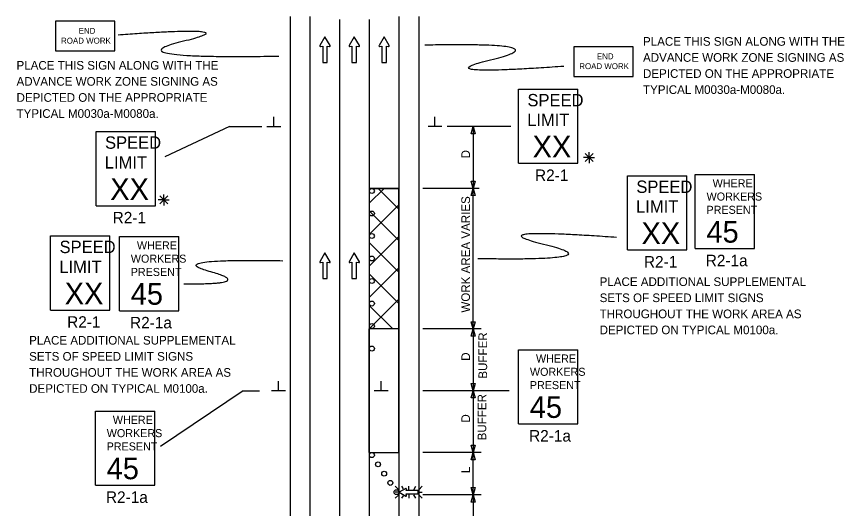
# Model space of a CAD drawing. Extents: x 16730 to 18475, y 5690 to 6927.
# Drawn here: x 16730 to 17399, y 6529 to 6927 of the extents above; entities that cross this region are included whole.
import ezdxf

# ---------------------------------------------------------------- set-up
doc = ezdxf.new("R2010")
doc.units = 0
for name, color, linetype in [('ALI_LEGAL_EX', 7, 'Continuous'), ('MT_SCRATCH_LEVEL_E', 7, 'Continuous'), ('PAVT_EDGE_EX', 7, 'Continuous'), ('TRAFFIC_SIGNS_PR', 7, 'Continuous'), ('TYPICAL_TEXT_DIMEN_PR', 7, 'Continuous')]:
    doc.layers.add(name, color=color, linetype=linetype)

msp = doc.modelspace()

# ---------------------------------------------------------------- linework, layer by layer
at = {"layer": 'ALI_LEGAL_EX'}
for p, q in [((16991.15, 6924.81), (16991.15, 6107.83)), ((17015.15, 6924.81), (17015.15, 6107.83))]:
    msp.add_line(p, q, dxfattribs=at)
for points in [[(16991.15, 6924.81), (16991.15, 6899.81)], [(17015.15, 6924.81), (17015.15, 6899.81)], [(16991.15, 6824.81), (16991.15, 6799.81)], [(17015.15, 6824.81), (17015.15, 6799.81)], [(16991.15, 6724.81), (16991.15, 6699.81)], [(17015.15, 6724.81), (17015.15, 6699.81)], [(16991.15, 6624.81), (16991.15, 6599.81)]]:
    msp.add_lwpolyline(points, dxfattribs=at)
at = {"layer": 'MT_SCRATCH_LEVEL_E'}
for p, q in [((16979.3, 6910.86), (16975.19, 6903.61)), ((16983.44, 6903.61), (16979.3, 6910.86)), ((17003, 6910.86), (16998.89, 6903.61)), ((17007.15, 6903.61), (17003, 6910.86)), ((17027.11, 6910.86), (17023, 6903.61)), ((17031.26, 6903.61), (17027.11, 6910.86)), ((16975.67, 6902.93), (16977.45, 6903.25)), ((16977.45, 6903.25), (16977.45, 6889.99)), ((16981.19, 6889.99), (16981.19, 6903.25)), ((16981.19, 6903.25), (16982.97, 6902.93)), ((16999.37, 6902.93), (17001.15, 6903.25)), ((17001.15, 6903.25), (17001.15, 6889.99)), ((17004.89, 6889.99), (17004.89, 6903.25)), ((17004.89, 6903.25), (17006.67, 6902.93)), ((17023.48, 6902.93), (17025.26, 6903.25)), ((17025.26, 6903.25), (17025.26, 6889.99)), ((17029, 6889.99), (17029, 6903.25)), ((17029, 6903.25), (17030.78, 6902.93)), ((16977.45, 6889.99), (16981.19, 6889.99)), ((17001.15, 6889.99), (17004.89, 6889.99)), ((17025.26, 6889.99), (17029, 6889.99)), ((16979.3, 6736.02), (16975.19, 6728.78)), ((16983.44, 6728.78), (16979.3, 6736.02)), ((17003, 6736.02), (16998.89, 6728.78)), ((17007.15, 6728.78), (17003, 6736.02)), ((16975.67, 6728.09), (16977.45, 6728.41)), ((16977.45, 6728.41), (16977.45, 6715.15)), ((16981.19, 6715.15), (16981.19, 6728.41)), ((16981.19, 6728.41), (16982.97, 6728.09)), ((16999.37, 6728.09), (17001.15, 6728.41)), ((17001.15, 6728.41), (17001.15, 6715.15)), ((17004.89, 6715.15), (17004.89, 6728.41)), ((17004.89, 6728.41), (17006.67, 6728.09)), ((16977.45, 6715.15), (16981.19, 6715.15)), ((17001.15, 6715.15), (17004.89, 6715.15))]:
    msp.add_line(p, q, dxfattribs=at)
for centre, start, end in [((16975.59, 6903.39), 150.42484, 279.96381), ((16983.04, 6903.39), 260.03619, 29.77312), ((16999.3, 6903.39), 150.42484, 279.96381), ((17006.74, 6903.39), 260.03619, 29.77312), ((17023.41, 6903.39), 150.42484, 279.96381), ((17030.85, 6903.39), 260.03619, 29.77312), ((16975.59, 6728.55), 150.42484, 279.96381), ((16983.04, 6728.55), 260.03619, 29.77312), ((16999.3, 6728.55), 150.42484, 279.96381), ((17006.74, 6728.55), 260.03619, 29.77312)]:
    msp.add_arc(centre, 0.463, start, end, dxfattribs=at)
at = {"layer": 'PAVT_EDGE_EX'}
for p, q in [((16951.15, 6927.15), (16951.15, 6107.83)), ((16967.15, 6927.15), (16967.15, 6107.83)), ((17039.15, 6927.15), (17039.15, 6107.83)), ((17055.15, 6927.15), (17055.15, 6107.83)), ((17039.15, 6788.15), (17015.15, 6788.15)), ((17015.15, 6788.15), (17039.15, 6788.15)), ((17015.15, 6776.25), (17027.06, 6788.15)), ((17039.15, 6771.35), (17022.34, 6788.15)), ((17039.15, 6674.43), (17039.15, 6788.15)), ((17015.15, 6750.8), (17039.15, 6774.8)), ((17039.15, 6745.89), (17015.15, 6769.89)), ((17015.15, 6725.34), (17039.15, 6749.34)), ((17039.15, 6720.43), (17015.15, 6744.43)), ((17015.15, 6699.89), (17039.15, 6723.89)), ((17039.15, 6694.98), (17015.15, 6718.98)), ((17015.15, 6674.43), (17039.15, 6698.43)), ((17034.24, 6674.43), (17015.15, 6693.52)), ((17015.15, 6574.43), (17039.15, 6574.43))]:
    msp.add_line(p, q, dxfattribs=at)
msp.add_lwpolyline([(17039.15, 6674.43), (17014.78, 6674.43), (17014.78, 6574.43), (17039.15, 6574.43)], close=True, dxfattribs=at)
at = {"layer": 'TRAFFIC_SIGNS_PR'}
for p, q in [((17135.85, 6868.44), (17183.85, 6868.44)), ((17135.85, 6808.44), (17135.85, 6868.44)), ((17183.85, 6808.44), (17183.85, 6868.44)), ((16794.22, 6834.12), (16842.22, 6834.12)), ((16794.22, 6774.12), (16794.22, 6834.12)), ((16842.22, 6774.12), (16842.22, 6834.12)), ((17135.85, 6808.44), (17183.85, 6808.44)), ((17223.93, 6798.4), (17271.93, 6798.4)), ((17223.93, 6738.4), (17223.93, 6798.4)), ((17271.93, 6738.4), (17271.93, 6798.4)), ((17278.73, 6799.44), (17326.73, 6799.44)), ((17278.73, 6739.44), (17278.73, 6799.44)), ((17326.73, 6739.44), (17326.73, 6799.44)), ((16794.22, 6774.12), (16842.22, 6774.12)), ((16757.41, 6749.7), (16805.41, 6749.7)), ((16757.41, 6689.7), (16757.41, 6749.7)), ((16805.41, 6689.7), (16805.41, 6749.7)), ((16813.05, 6749.19), (16861.05, 6749.19)), ((16813.05, 6689.19), (16813.05, 6749.19)), ((16861.05, 6689.19), (16861.05, 6749.19)), ((17223.93, 6738.4), (17271.93, 6738.4)), ((17278.73, 6739.44), (17326.73, 6739.44)), ((16757.41, 6689.7), (16805.41, 6689.7)), ((16813.05, 6689.19), (16861.05, 6689.19)), ((17135.85, 6657.64), (17183.85, 6657.64)), ((17135.85, 6597.64), (17135.85, 6657.64)), ((17183.85, 6597.64), (17183.85, 6657.64)), ((16793.57, 6608.02), (16841.57, 6608.02)), ((16793.57, 6548.02), (16793.57, 6608.02)), ((16841.57, 6548.02), (16841.57, 6608.02)), ((17135.85, 6597.64), (17183.85, 6597.64)), ((16793.57, 6548.02), (16841.57, 6548.02)), ((17036.14, 6547.12), (17038.96, 6544.3)), ((17038.96, 6542.27), (17036.14, 6542.27)), ((17042.86, 6544.94), (17041.6, 6547.12)), ((17047.05, 6544.3), (17047.05, 6547.12)), ((17051.18, 6544.3), (17052.81, 6547.12)), ((17055.13, 6544.3), (17057.95, 6547.12)), ((17055.13, 6542.27), (17057.95, 6542.27)), ((17036.14, 6537.42), (17038.96, 6540.24)), ((17041.58, 6537.42), (17042.78, 6539.51)), ((17047.05, 6540.24), (17047.05, 6537.42)), ((17052.83, 6537.42), (17051.21, 6540.24)), ((17055.13, 6540.24), (17057.95, 6537.42))]:
    msp.add_line(p, q, dxfattribs=at)
for points in [[(16761.34, 6899.29), (16809.34, 6899.29), (16809.34, 6923.29), (16761.34, 6923.29)], [(17180.47, 6878.69), (17228.47, 6878.69), (17228.47, 6902.69), (17180.47, 6902.69)]]:
    msp.add_lwpolyline(points, close=True, dxfattribs=at)
for points in [[(17044.72, 6545.29), (17039.41, 6542.27), (17044.72, 6539.23)], [(17045.22, 6539.59), (17044.99, 6540.89), (17054.71, 6540.89), (17054.71, 6543.63), (17044.99, 6543.63), (17045.22, 6544.93)]]:
    msp.add_lwpolyline(points, dxfattribs=at)
for centre in [(17017.25, 6786.03), (17017.25, 6767.82), (17017.25, 6749.6), (17017.25, 6731.39), (17017.25, 6713.18), (17017.25, 6694.96), (17017.25, 6676.75), (17017.25, 6658.53), (17017.25, 6572.38), (17022.22, 6564.87), (17027.19, 6557.36), (17032.16, 6549.86), (17037.13, 6542.36)]:
    msp.add_circle(centre, 2, dxfattribs=at)
for centre, start, end in [((17044.89, 6544.99), 350.73078, 118.89165), ((17044.88, 6539.53), 241.48329, 9.95933)]:
    msp.add_arc(centre, 0.341, start, end, dxfattribs=at)
for points in [[(16812.02, 6912.43), (16920.52, 6920.56), (16806.61, 6892.97), (16942.08, 6895.14)], [(17172.4, 6886.84), (17057.17, 6878.6), (17171.08, 6906.19), (17060.06, 6904.02)], [(17215.2, 6748.42), (17099.98, 6756.66), (17213.88, 6729.08), (17102.87, 6731.25)], [(16865.23, 6710.91), (16924.03, 6710.39), (16847.51, 6731.53), (16945.22, 6729.62)]]:
    msp.add_open_spline(points, degree=2, dxfattribs=at)
at = {"layer": 'TYPICAL_TEXT_DIMEN_PR'}
for p, q in [((16938.03, 6838.15), (16938.03, 6845.94)), ((17068.28, 6838.15), (17068.28, 6845.94)), ((16902.15, 6838.15), (16849.83, 6813.69)), ((16902.15, 6838.15), (16928.15, 6838.15)), ((16932.4, 6838.15), (16943.65, 6838.15)), ((17073.9, 6838.15), (17062.65, 6838.15)), ((17129.64, 6838.15), (17078.15, 6838.15)), ((17097.58, 6832.29), (17099.15, 6838.15)), ((17099.15, 6838.15), (17100.72, 6832.29)), ((17099.15, 6838.15), (17099.15, 6788.15)), ((17099.15, 6832.29), (17097.58, 6832.29)), ((17100.72, 6832.29), (17099.15, 6832.29)), ((17192.94, 6813.05), (17192.94, 6817.5)), ((17192.94, 6813.05), (17188.41, 6813.05)), ((17189.76, 6816.24), (17196.13, 6809.86)), ((17196.13, 6816.24), (17189.76, 6809.86)), ((17192.94, 6813.05), (17196.13, 6813.05)), ((17192.94, 6813.05), (17197.42, 6813.05)), ((17192.94, 6813.05), (17192.94, 6808.55)), ((17099.15, 6788.15), (17097.58, 6794.02)), ((17097.58, 6794.02), (17099.15, 6794.02)), ((17099.15, 6794.02), (17100.72, 6794.02)), ((17100.72, 6794.02), (17099.15, 6788.15)), ((16848.92, 6778.85), (16848.92, 6783.3)), ((17104.15, 6788.15), (17058.45, 6788.15)), ((17097.58, 6782.29), (17099.15, 6788.15)), ((17099.15, 6674.43), (17099.15, 6788.15)), ((17099.15, 6788.15), (17100.72, 6782.29)), ((16848.92, 6778.85), (16844.39, 6778.85)), ((16845.73, 6782.03), (16852.11, 6775.66)), ((16852.11, 6782.03), (16845.73, 6775.66)), ((16848.92, 6778.85), (16852.11, 6778.85)), ((16848.92, 6778.85), (16853.4, 6778.85)), ((16848.92, 6778.85), (16848.92, 6774.35)), ((17099.15, 6782.29), (17097.58, 6782.29)), ((17100.72, 6782.29), (17099.15, 6782.29)), ((17099.15, 6674.43), (17097.58, 6680.29)), ((17097.58, 6680.29), (17099.15, 6680.29)), ((17099.15, 6680.29), (17100.72, 6680.29)), ((17100.72, 6680.29), (17099.15, 6674.43)), ((17105.72, 6674.43), (17058.45, 6674.43)), ((17097.58, 6668.57), (17099.15, 6674.43)), ((17099.15, 6674.43), (17099.15, 6624.43)), ((17099.15, 6674.43), (17100.72, 6668.57)), ((17099.15, 6668.57), (17097.58, 6668.57)), ((17100.72, 6668.57), (17099.15, 6668.57)), ((16941.77, 6624.43), (16941.77, 6632.22)), ((17024.65, 6624.43), (17024.65, 6632.22)), ((17099.15, 6624.43), (17097.58, 6630.29)), ((17097.58, 6630.29), (17099.15, 6630.29)), ((17099.15, 6630.29), (17100.72, 6630.29)), ((17100.72, 6630.29), (17099.15, 6624.43)), ((16913.1, 6624.43), (16846.22, 6579.29)), ((16913.1, 6624.43), (16926.27, 6624.43)), ((16947.39, 6624.43), (16936.14, 6624.43)), ((17030.28, 6624.43), (17019.03, 6624.43)), ((17128.22, 6624.43), (17058.45, 6624.43)), ((17097.58, 6618.57), (17099.15, 6624.43)), ((17099.15, 6624.43), (17099.15, 6574.43)), ((17099.15, 6624.43), (17100.72, 6618.57)), ((17099.15, 6618.57), (17097.58, 6618.57)), ((17100.72, 6618.57), (17099.15, 6618.57)), ((17099.15, 6574.43), (17097.58, 6580.29)), ((17097.58, 6580.29), (17099.15, 6580.29)), ((17099.15, 6580.29), (17100.72, 6580.29)), ((17100.72, 6580.29), (17099.15, 6574.43)), ((17105.72, 6574.43), (17058.45, 6574.43)), ((17097.58, 6568.57), (17099.15, 6574.43)), ((17099.15, 6540.24), (17099.15, 6574.43)), ((17099.15, 6574.43), (17100.72, 6568.57)), ((17099.15, 6568.57), (17097.58, 6568.57)), ((17100.72, 6568.57), (17099.15, 6568.57)), ((17099.15, 6540.24), (17097.58, 6546.1)), ((17097.58, 6546.1), (17099.15, 6546.1)), ((17099.15, 6546.1), (17100.72, 6546.1)), ((17100.72, 6546.1), (17099.15, 6540.24)), ((17105.72, 6540.24), (17058.45, 6540.24)), ((17097.58, 6534.38), (17099.15, 6540.24)), ((17099.15, 6540.24), (17099.15, 6490.24)), ((17099.15, 6540.24), (17100.72, 6534.38)), ((17099.15, 6534.38), (17097.58, 6534.38)), ((17100.72, 6534.38), (17099.15, 6534.38))]:
    msp.add_line(p, q, dxfattribs=at)

# ---------------------------------------------------------------- texts
at = {"layer": 'TRAFFIC_SIGNS_PR'}
for s, height, p in [('END', 4.789, (16780.09, 6913.21)), ('PLACE THIS SIGN ALONG WITH THE', 7, (17236.55, 6903.54)), ('ROAD WORK', 4.789, (16765.85, 6905.23)), ('END', 4.789, (17199.22, 6892.6)), ('ADVANCE WORK ZONE SIGNING AS', 7, (17236.55, 6890.54)), ('PLACE THIS SIGN ALONG WITH THE', 7, (16729.82, 6884.19)), ('ROAD WORK', 4.789, (17184.98, 6884.62)), ('DEPICTED ON THE APPROPRIATE', 7, (17236.55, 6877.54)), ('ADVANCE WORK ZONE SIGNING AS', 7, (16729.82, 6871.19)), ('TYPICAL M0030a-M0080a.', 7, (17236.55, 6864.54)), ('DEPICTED ON THE APPROPRIATE', 7, (16729.82, 6858.19)), ('SPEED', 10, (17143.06, 6854.52)), ('TYPICAL M0030a-M0080a.', 7, (16729.82, 6845.19)), ('LIMIT', 10, (17142.86, 6838.52)), ('SPEED', 10, (16801.42, 6820.2)), ('XX', 17.538, (17147.24, 6813.14)), ('LIMIT', 10, (16801.22, 6804.2)), ('R2-1', 9.3, (17149.19, 6794.14)), ('XX', 17.538, (16805.61, 6778.82)), ('SPEED', 10, (17231.14, 6784.48)), ('WHERE', 6.5, (17292.86, 6789.04)), ('WORKERS', 6.5, (17287.96, 6778.29)), ('LIMIT', 10, (17230.94, 6768.48)), ('PRESENT', 6.5, (17287.87, 6767.54)), ('R2-1', 9.3, (16807.56, 6759.83)), ('XX', 17.538, (17235.32, 6743.1)), ('45', 17.538, (17287.86, 6744.25)), ('SPEED', 10, (16764.62, 6735.78)), ('WHERE', 6.5, (16827.19, 6738.79)), ('LIMIT', 10, (16764.42, 6719.78)), ('WORKERS', 6.5, (16822.28, 6728.04)), ('R2-1', 9.3, (17237.28, 6724.11)), ('R2-1a', 9.3, (17287.29, 6725.14)), ('PRESENT', 6.5, (16822.2, 6717.29)), ('XX', 17.538, (16768.8, 6694.4)), ('45', 17.538, (16822.19, 6694.01)), ('PLACE ADDITIONAL SUPPLEMENTAL', 7, (17201.45, 6709.13)), ('SETS OF SPEED LIMIT SIGNS', 7, (17201.45, 6696.13)), ('THROUGHOUT THE WORK AREA AS', 7, (17201.45, 6683.13)), ('R2-1', 9.3, (16770.76, 6675.4)), ('R2-1a', 9.3, (16821.62, 6674.89)), ('DEPICTED ON TYPICAL M0100a.', 7, (17201.45, 6670.13)), ('PLACE ADDITIONAL SUPPLEMENTAL', 7, (16740.02, 6661.74)), ('SETS OF SPEED LIMIT SIGNS', 7, (16740.02, 6648.74)), ('WHERE', 6.5, (17149.99, 6647.25)), ('THROUGHOUT THE WORK AREA AS', 7, (16740.02, 6635.74)), ('WORKERS', 6.5, (17145.08, 6636.5)), ('DEPICTED ON TYPICAL M0100a.', 7, (16740.02, 6622.74)), ('PRESENT', 6.5, (17144.99, 6625.75)), ('45', 17.538, (17144.98, 6602.46)), ('WHERE', 6.5, (16807.71, 6597.63)), ('WORKERS', 6.5, (16802.8, 6586.88)), ('R2-1a', 9.3, (17144.42, 6583.34)), ('PRESENT', 6.5, (16802.71, 6576.13)), ('45', 17.538, (16802.7, 6552.84)), ('R2-1a', 9.3, (16802.14, 6533.72))]:
    msp.add_text(s, height=height, dxfattribs=at).set_placement(p)
at = {"layer": 'TYPICAL_TEXT_DIMEN_PR'}
for s, p in [('D', (17096.59, 6812.37)), ('WORK AREA VARIES', (17096.59, 6687.65)), ('BUFFER', (17110.46, 6634.21)), ('D', (17096.59, 6648.65)), ('BUFFER', (17109.77, 6584.29)), ('D', (17096.59, 6598.65)), ('L', (17096.59, 6557.72))]:
    msp.add_text(s, height=7, rotation=90, dxfattribs=at).set_placement(p)

doc.saveas('drawing.dxf')
